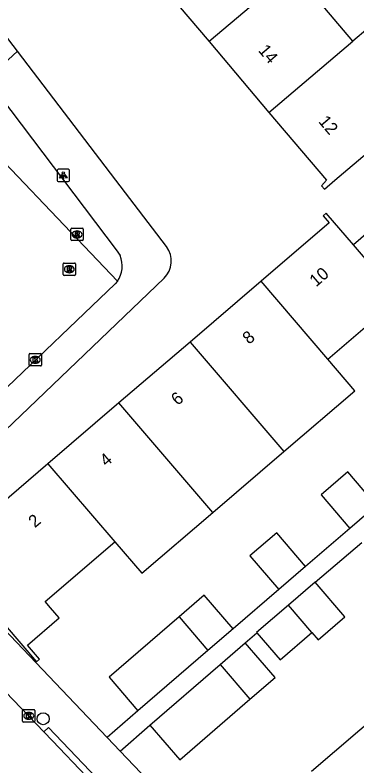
# Model space of a CAD drawing. Extents: x 159353 to 160616, y 385893 to 387321.
# Drawn here: x 160032 to 160059.7, y 386452.7 to 386513.4 of the extents above; entities that cross this region are included whole.
import ezdxf

# ---------------------------------------------------------------- set-up
doc = ezdxf.new("R2010")
doc.units = 0
for name, color, linetype in [('IMGEO_Boom', 7, 'Continuous'), ('IMGEO_Groenvoorziening', 7, 'Continuous'), ('IMGEO_Kolk', 7, 'Continuous'), ('IMGEO_Lichtpunt', 7, 'Continuous'), ('IMGEO_Pand', 7, 'Continuous'), ('IMGEO_Pand_nummerreeks', 7, 'Continuous'), ('IMGEO_Rijbaan_lokaal_open', 7, 'Continuous'), ('IMGEO_Rioolput', 7, 'Continuous'), ('IMGEO_Voetpad_open', 7, 'Continuous')]:
    doc.layers.add(name, color=color, linetype=linetype)

msp = doc.modelspace()

# ---------------------------------------------------------------- linework, layer by layer
at = {"layer": 'IMGEO_Boom'}
msp.add_circle((160034.311, 386456.481), 0.489, dxfattribs=at)
at = {"layer": 'IMGEO_Groenvoorziening'}
msp.add_lwpolyline([(160026.677, 386506.148), (160026.84, 386505.979), (160040.317, 386491.842)], dxfattribs=at)
at = {"layer": 'IMGEO_Kolk'}
for p, q in [((160033.169, 386485.066), (160033.169, 386485.918)), ((160033.244, 386485.992), (160034.096, 386485.992)), ((160033.657, 386485.772), (160033.682, 386485.772)), ((160034.17, 386485.918), (160034.17, 386485.066)), ((160033.68, 386485.212), (160033.655, 386485.212)), ((160034.096, 386484.992), (160033.244, 386484.992)), ((160032.645, 386456.288), (160032.645, 386457.14)), ((160032.72, 386457.214), (160033.572, 386457.214)), ((160033.646, 386457.14), (160033.646, 386456.288)), ((160033.133, 386456.994), (160033.158, 386456.994)), ((160033.572, 386456.214), (160032.72, 386456.214)), ((160033.156, 386456.434), (160033.131, 386456.434))]:
    msp.add_line(p, q, dxfattribs=at)
for points in [[(160033.169, 386485.066), (160033.169, 386485.918)], [(160033.244, 386485.992), (160034.096, 386485.992)], [(160033.49, 386485.692), (160033.613, 386485.692), (160033.613, 386485.541), (160033.743, 386485.692), (160033.907, 386485.692), (160033.761, 386485.541), (160033.914, 386485.292), (160033.762, 386485.292), (160033.677, 386485.456), (160033.613, 386485.389), (160033.613, 386485.292), (160033.49, 386485.292), (160033.49, 386485.692)], [(160034.17, 386485.918), (160034.17, 386485.066)], [(160034.096, 386484.992), (160033.244, 386484.992)], [(160032.645, 386456.288), (160032.645, 386457.14)], [(160032.72, 386457.214), (160033.572, 386457.214)], [(160033.646, 386457.14), (160033.646, 386456.288)], [(160032.966, 386456.914), (160033.089, 386456.914), (160033.089, 386456.763), (160033.219, 386456.914), (160033.383, 386456.914), (160033.237, 386456.763), (160033.39, 386456.514), (160033.238, 386456.514), (160033.153, 386456.678), (160033.089, 386456.611), (160033.089, 386456.514), (160032.966, 386456.514), (160032.966, 386456.914)], [(160033.572, 386456.214), (160032.72, 386456.214)]]:
    msp.add_lwpolyline(points, dxfattribs=at)
for centre, start, end in [((160033.246, 386485.916), 91.55205, 178.44795), ((160033.246, 386485.916), 91.55205, 178.44795), ((160034.094, 386485.916), 1.55205, 88.44795), ((160034.094, 386485.916), 1.55205, 88.44795), ((160033.246, 386485.068), 181.55205, 268.44795), ((160033.246, 386485.068), 181.55205, 268.44795), ((160034.094, 386485.068), 271.55205, 358.44795), ((160034.094, 386485.068), 271.55205, 358.44795), ((160032.722, 386457.138), 91.55205, 178.44795), ((160032.722, 386457.138), 91.55205, 178.44795), ((160033.57, 386457.138), 1.55205, 88.44795), ((160033.57, 386457.138), 1.55205, 88.44795), ((160032.722, 386456.29), 181.55205, 268.44795), ((160032.722, 386456.29), 181.55205, 268.44795), ((160033.57, 386456.29), 271.55205, 358.44795), ((160033.57, 386456.29), 271.55205, 358.44795)]:
    msp.add_arc(centre, 0.0765, start, end, dxfattribs=at)
for centre, major_axis, ratio, start_param, end_param in [((160033.656, 386485.492), (-0.387, 0.002), 0.722429, 4.712389, 7.853982), ((160033.681, 386485.492), (-0.39, 0.002), 0.717154, 1.570796, 4.712389), ((160033.132, 386456.714), (-0.387, 0.002), 0.722429, 4.712389, 7.853982), ((160033.157, 386456.714), (-0.39, 0.002), 0.717154, 1.570796, 4.712389)]:
    msp.add_ellipse(centre, major_axis=major_axis, ratio=ratio, start_param=start_param, end_param=end_param, dxfattribs=at)
at = {"layer": 'IMGEO_Lichtpunt'}
for p, q in [((160036.341, 386500.889), (160035.533, 386500.889)), ((160036.341, 386500.889), (160035.533, 386500.889)), ((160035.439, 386500.794), (160035.439, 386499.987)), ((160035.439, 386500.794), (160035.439, 386499.987)), ((160036.435, 386499.987), (160036.435, 386500.794)), ((160036.435, 386499.987), (160036.435, 386500.794)), ((160035.533, 386499.893), (160036.341, 386499.893)), ((160035.533, 386499.893), (160036.341, 386499.893))]:
    msp.add_line(p, q, dxfattribs=at)
for points in [[(160035.813, 386500.458), (160035.852, 386500.43), (160035.664, 386500.168), (160035.626, 386500.195), (160035.813, 386500.458)], [(160035.915, 386500.41), (160035.962, 386500.41), (160035.962, 386500.088), (160035.915, 386500.088), (160035.915, 386500.41)], [(160036.025, 386500.43), (160036.063, 386500.457), (160036.25, 386500.195), (160036.211, 386500.167), (160036.025, 386500.43)]]:
    msp.add_lwpolyline(points, dxfattribs=at)
msp.add_circle((160035.938, 386500.592), 0.0994, dxfattribs=at)
for centre, start, end in [((160035.533, 386500.794), 90, 180), ((160035.533, 386500.794), 90, 180), ((160036.341, 386500.794), 0, 90), ((160036.341, 386500.794), 0, 90), ((160035.533, 386499.987), 180, 270), ((160035.533, 386499.987), 180, 270), ((160036.341, 386499.987), 270, 0), ((160036.341, 386499.987), 270, 360)]:
    msp.add_arc(centre, 0.0946, start, end, dxfattribs=at)
at = {"layer": 'IMGEO_Pand'}
for points in [[(160042.876, 386516.926), (160047.721, 386511.21)], [(160054.511, 386516.964), (160047.721, 386511.21)], [(160059.354, 386511.248), (160054.511, 386516.964)], [(160052.565, 386505.494), (160057.221, 386500), (160056.817, 386499.56), (160057.051, 386499.284), (160057.896, 386500), (160060.866, 386502.517), (160064.293, 386505.421), (160066.708, 386507.467), (160061.769, 386513.295), (160059.354, 386511.248)], [(160047.721, 386511.21), (160052.565, 386505.494)], [(160052.565, 386505.494), (160059.354, 386511.248)], [(160059.385, 386494.775), (160057.196, 386497.334), (160056.951, 386497.124), (160057.431, 386496.563), (160051.93, 386491.851)], [(160061.78, 386496.826), (160059.385, 386494.775)], [(160063.081, 386490.474), (160059.385, 386494.775)], [(160051.93, 386491.851), (160046.185, 386486.93)], [(160057.33, 386485.549), (160051.93, 386491.851)], [(160057.33, 386485.549), (160062.789, 386490.224)], [(160046.185, 386486.93), (160040.439, 386482.008)], [(160046.185, 386486.93), (160053.771, 386478.075)], [(160053.771, 386478.075), (160059.518, 386482.997), (160057.33, 386485.549)], [(160040.439, 386482.008), (160034.693, 386477.087)], [(160048.025, 386473.154), (160040.439, 386482.008)], [(160048.025, 386473.154), (160053.771, 386478.075)], [(160034.693, 386477.087), (160030.753, 386473.712), (160030.35, 386474.182), (160028.435, 386472.542), (160030.166, 386470.522), (160027.584, 386468.311), (160033.777, 386461.08), (160034.021, 386461.289), (160033.046, 386462.429), (160035.611, 386464.626), (160034.9, 386465.456), (160034.465, 386465.964), (160040.093, 386470.785)], [(160034.693, 386477.087), (160040.093, 386470.785)], [(160061.268, 386473.712), (160058.939, 386476.429), (160056.775, 386474.574), (160059.104, 386471.857)], [(160061.268, 386473.712), (160059.104, 386471.857)], [(160040.093, 386470.785), (160042.279, 386468.233), (160048.025, 386473.154)], [(160055.522, 386468.79), (160053.193, 386471.507), (160051.029, 386469.652), (160053.358, 386466.935)], [(160055.522, 386468.79), (160053.358, 386466.935)], [(160056.309, 386467.516), (160054.14, 386465.656)], [(160056.038, 386463.441), (160056.531, 386462.866), (160058.701, 386464.726), (160056.309, 386467.516)], [(160049.665, 386463.758), (160047.331, 386466.466), (160045.297, 386464.712)], [(160054.14, 386465.656), (160051.57, 386463.453), (160051.589, 386463.43)], [(160056.038, 386463.441), (160054.14, 386465.656)], [(160045.297, 386464.712), (160039.636, 386459.831), (160041.971, 386457.123)], [(160045.297, 386464.712), (160047.623, 386461.997)], [(160049.665, 386463.758), (160047.623, 386461.997)], [(160051.589, 386463.43), (160053.469, 386461.238), (160056.038, 386463.441)], [(160048.617, 386460.855), (160050.647, 386462.609)], [(160051.019, 386458.05), (160053.061, 386459.815), (160050.647, 386462.609)], [(160047.623, 386461.997), (160041.971, 386457.123)], [(160042.944, 386455.953), (160048.617, 386460.855)], [(160048.617, 386460.855), (160051.019, 386458.05)], [(160042.944, 386455.953), (160045.358, 386453.159), (160051.019, 386458.05)], [(160061.761, 386457.132), (160056.016, 386452.213)]]:
    msp.add_lwpolyline(points, dxfattribs=at)
at = {"layer": 'IMGEO_Rijbaan_lokaal_open'}
for points in [[(160034.378, 386455.424), (160009.601, 386481.243), (160007.388, 386483.587)], [(160040.522, 386448.973), (160035.066, 386454.705), (160034.378, 386455.424)]]:
    msp.add_lwpolyline(points, dxfattribs=at)
at = {"layer": 'IMGEO_Rioolput'}
for p, q in [((160036.554, 386495.204), (160036.554, 386496.056)), ((160036.629, 386496.13), (160037.481, 386496.13)), ((160037.555, 386496.056), (160037.555, 386495.204)), ((160037.042, 386495.91), (160037.067, 386495.91)), ((160037.481, 386495.13), (160036.629, 386495.13)), ((160037.065, 386495.35), (160037.04, 386495.35)), ((160035.923, 386492.389), (160035.923, 386493.241)), ((160035.998, 386493.315), (160036.85, 386493.315)), ((160036.411, 386493.095), (160036.436, 386493.095)), ((160036.924, 386493.241), (160036.924, 386492.389)), ((160036.434, 386492.535), (160036.409, 386492.535)), ((160036.85, 386492.315), (160035.998, 386492.315))]:
    msp.add_line(p, q, dxfattribs=at)
for points in [[(160036.554, 386495.204), (160036.554, 386496.056)], [(160036.629, 386496.13), (160037.481, 386496.13)], [(160037.555, 386496.056), (160037.555, 386495.204)], [(160037.143, 386495.828), (160036.891, 386495.83), (160036.891, 386495.43)], [(160036.891, 386495.43), (160037.015, 386495.43), (160037.015, 386495.592), (160037.026, 386495.592)], [(160037.069, 386495.749), (160037.015, 386495.749), (160037.015, 386495.668)], [(160037.015, 386495.668), (160037.067, 386495.668)], [(160037.073, 386495.563), (160037.144, 386495.43), (160037.284, 386495.43), (160037.219, 386495.556)], [(160037.481, 386495.13), (160036.629, 386495.13)], [(160035.923, 386492.389), (160035.923, 386493.241)], [(160035.998, 386493.315), (160036.85, 386493.315)], [(160036.512, 386493.013), (160036.26, 386493.015), (160036.26, 386492.615)], [(160036.924, 386493.241), (160036.924, 386492.389)], [(160036.26, 386492.615), (160036.384, 386492.615), (160036.384, 386492.777), (160036.395, 386492.777)], [(160036.438, 386492.934), (160036.384, 386492.934), (160036.384, 386492.853)], [(160036.384, 386492.853), (160036.436, 386492.853)], [(160036.442, 386492.748), (160036.513, 386492.615), (160036.653, 386492.615), (160036.588, 386492.741)], [(160036.85, 386492.315), (160035.998, 386492.315)]]:
    msp.add_lwpolyline(points, dxfattribs=at)
for centre, radius, start, end in [((160036.631, 386496.054), 0.0765, 91.55205, 178.44795), ((160036.631, 386496.054), 0.0765, 91.55205, 178.44795), ((160037.479, 386496.054), 0.0765, 1.55205, 88.44795), ((160037.479, 386496.054), 0.0765, 1.55205, 88.44795), ((160037.025, 386495.539), 0.0533, 26.02933, 88.69889), ((160037.051, 386495.857), 0.19, 274.7715, 282.96867), ((160037.075, 386495.653), 0.0964, 77.00612, 93.18647), ((160037.089, 386495.71), 0.0378, 276.66336, 79.67722), ((160037.142, 386495.718), 0.109, 350.36119, 89.41601), ((160037.14, 386495.718), 0.112, 277.58423, 350.98172), ((160037.124, 386495.503), 0.108, 29.51342, 73.79051), ((160036.631, 386495.206), 0.0765, 181.55205, 268.44795), ((160036.631, 386495.206), 0.0765, 181.55205, 268.44795), ((160037.479, 386495.206), 0.0765, 271.55205, 358.44795), ((160037.479, 386495.206), 0.0765, 271.55205, 358.44795), ((160036, 386493.239), 0.0765, 91.55205, 178.44795), ((160036, 386493.239), 0.0765, 91.55205, 178.44795), ((160036.511, 386492.903), 0.109, 350.36119, 89.41601), ((160036.848, 386493.239), 0.0765, 1.55205, 88.44795), ((160036.848, 386493.239), 0.0765, 1.55205, 88.44795), ((160036, 386492.391), 0.0765, 181.55205, 268.44795), ((160036, 386492.391), 0.0765, 181.55205, 268.44795), ((160036.394, 386492.724), 0.0533, 26.02933, 88.69889), ((160036.42, 386493.042), 0.19, 274.7715, 282.96867), ((160036.444, 386492.838), 0.0964, 77.00612, 93.18647), ((160036.458, 386492.895), 0.0378, 276.66336, 79.67722), ((160036.509, 386492.903), 0.112, 277.58423, 350.98172), ((160036.493, 386492.688), 0.108, 29.51342, 73.79051), ((160036.848, 386492.391), 0.0765, 271.55205, 358.44795), ((160036.848, 386492.391), 0.0765, 271.55205, 358.44795)]:
    msp.add_arc(centre, radius, start, end, dxfattribs=at)
for centre, major_axis, ratio, start_param, end_param in [((160037.041, 386495.63), (-0.387, 0.002), 0.722429, 4.712389, 7.853982), ((160037.066, 386495.63), (-0.39, 0.002), 0.717154, 1.570796, 4.712389), ((160036.41, 386492.815), (-0.387, 0.002), 0.722429, 4.712389, 7.853982), ((160036.435, 386492.815), (-0.39, 0.002), 0.717154, 1.570796, 4.712389)]:
    msp.add_ellipse(centre, major_axis=major_axis, ratio=ratio, start_param=start_param, end_param=end_param, dxfattribs=at)
at = {"layer": 'IMGEO_Voetpad_open'}
for points in [[(160032.226, 386510.438), (160009.619, 386540.052)], [(160032.226, 386510.438), (160029.258, 386507.683)], [(160044.282, 386494.645), (160040.194, 386500), (160032.226, 386510.438)], [(160030.329, 386507.303), (160030.537, 386507.114), (160030.853, 386506.739), (160040.2, 386494.386), (160040.527, 386493.916)], [(160025.427, 386474.216), (160044.084, 386492.088)], [(160040.317, 386491.842), (160040.137, 386491.644), (160030.759, 386482.699)], [(160059.104, 386471.857), (160055.522, 386468.79)], [(160056.309, 386467.516), (160060.065, 386470.73)], [(160039.476, 386454.971), (160025.326, 386469.813)], [(160053.358, 386466.935), (160049.665, 386463.758)], [(160050.647, 386462.609), (160051.589, 386463.43)], [(160041.971, 386457.123), (160039.476, 386454.971)], [(160040.529, 386453.866), (160042.944, 386455.953)], [(160034.378, 386455.424), (160034.737, 386455.771), (160040.881, 386449.32), (160040.522, 386448.973)], [(160039.476, 386454.971), (160040.529, 386453.866)], [(160055.653, 386438.003), (160040.529, 386453.866)]]:
    msp.add_lwpolyline(points, dxfattribs=at)
for centre, radius, start, end in [((160042.752, 386493.477), 1.925, 313.79046, 37.35387), ((160038.604, 386493.063), 2.104, 324.51958, 23.91702)]:
    msp.add_arc(centre, radius, start, end, dxfattribs=at)

# ---------------------------------------------------------------- texts
at = {"layer": 'IMGEO_Pand_nummerreeks'}
for s, rotation, p in [('14', 310.28197, (160051.647, 386510.474)), ('12', 310.28197, (160056.514, 386504.732)), ('10', 40.58133, (160056.37, 386491.336)), ('8', 40.5826, (160050.952, 386486.694)), ('6', 40.5826, (160045.182, 386481.752)), ('4', 40.58133, (160039.414, 386476.812)), ('2', 40.58133, (160033.644, 386471.869))]:
    msp.add_text(s, height=1, rotation=rotation, dxfattribs=at).set_placement(p)

doc.saveas('drawing.dxf')
